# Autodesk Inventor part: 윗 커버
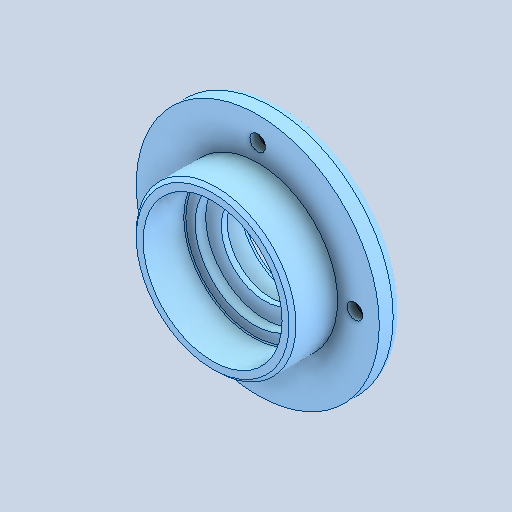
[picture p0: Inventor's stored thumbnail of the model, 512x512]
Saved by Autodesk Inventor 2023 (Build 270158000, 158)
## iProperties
Created: 2025-04
Part Number: 윗 커버
Material: 알루미늄 6061
Document SubType Name: Modeling
Designer: User
Density: 2.71 g/cm^3
Appearance: 기본값
Company: 한국ATC센터
Author: jhkim
Revision Number: 1
Sending System: Autodesk Inventor 2026
Preprocessor: ST-DEVELOPER v20.1
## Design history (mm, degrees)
feature "솔리드1"
node "솔리드2"
